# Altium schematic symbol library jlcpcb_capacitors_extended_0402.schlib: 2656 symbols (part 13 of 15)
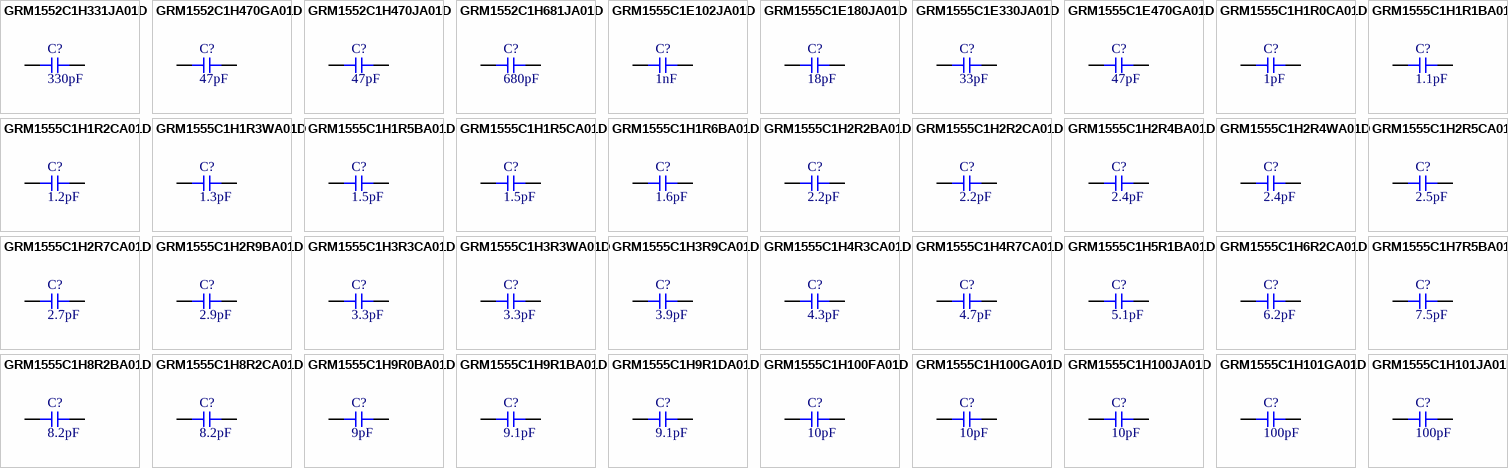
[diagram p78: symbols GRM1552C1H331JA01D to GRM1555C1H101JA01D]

## GRM1555C1H4R3CA01D
designator C?  Capacitance: 4.3pF  (hidden comment: *)
Capacitor, Ceramic (MLCC), 4.3pF, ±0.25pF, 50V, C0G, ±0.25pF, SMD 0402; Manufacturer: Murata Electronics; Manufacturer Part Number: GRM1555C1H4R3CA01D
footprint CAP-0402 (0402 (1005M) Capacitor)
pins: 1, 2

## GRM1555C1H4R7CA01D
designator C?  Capacitance: 4.7pF  (hidden comment: *)
Capacitor, Ceramic (MLCC), 4.7pF, ±0.25pF, 50V, C0G, ±0.25pF, SMD 0402; Manufacturer: Murata Electronics; Manufacturer Part Number: GRM1555C1H4R7CA01D
footprint CAP-0402 (0402 (1005M) Capacitor)
pins: 1, 2

## GRM1555C1H5R1BA01D
designator C?  Capacitance: 5.1pF  (hidden comment: *)
Capacitor, Ceramic (MLCC), 5.1pF, ±0.1pF, 50V, C0G, ±0.1pF, SMD 0402; Manufacturer: Murata Electronics; Manufacturer Part Number: GRM1555C1H5R1BA01D
footprint CAP-0402 (0402 (1005M) Capacitor)
pins: 1, 2

## GRM1555C1H6R2CA01D
designator C?  Capacitance: 6.2pF  (hidden comment: *)
Capacitor, Ceramic (MLCC), 6.2pF, ±0.25pF, 50V, C0G, ±0.25pF, SMD 0402; Manufacturer: Murata Electronics; Manufacturer Part Number: GRM1555C1H6R2CA01D
footprint CAP-0402 (0402 (1005M) Capacitor)
pins: 1, 2

## GRM1555C1H7R5BA01D
designator C?  Capacitance: 7.5pF  (hidden comment: *)
Capacitor, Ceramic (MLCC), 7.5pF, ±0.1pF, 50V, C0G, ±0.1pF, SMD 0402; Manufacturer: Murata Electronics; Manufacturer Part Number: GRM1555C1H7R5BA01D
footprint CAP-0402 (0402 (1005M) Capacitor)
pins: 1, 2

## GRM1555C1H8R2BA01D
designator C?  Capacitance: 8.2pF  (hidden comment: *)
Capacitor, Ceramic (MLCC), 8.2pF, ±0.1pF, 50V, C0G, ±0.1pF, SMD 0402; Manufacturer: Murata Electronics; Manufacturer Part Number: GRM1555C1H8R2BA01D
footprint CAP-0402 (0402 (1005M) Capacitor)
pins: 1, 2

## GRM1555C1H8R2CA01D
designator C?  Capacitance: 8.2pF  (hidden comment: *)
Capacitor, Ceramic (MLCC), 8.2pF, ±0.25pF, 50V, C0G, ±0.25pF, SMD 0402; Manufacturer: Murata Electronics; Manufacturer Part Number: GRM1555C1H8R2CA01D
footprint CAP-0402 (0402 (1005M) Capacitor)
pins: 1, 2

## GRM1555C1H9R0BA01D
designator C?  Capacitance: 9pF  (hidden comment: *)
Capacitor, Ceramic (MLCC), 9pF, ±0.1pF, 50V, C0G, ±0.1pF, SMD 0402; Manufacturer: Murata Electronics; Manufacturer Part Number: GRM1555C1H9R0BA01D
footprint CAP-0402 (0402 (1005M) Capacitor)
pins: 1, 2

## GRM1555C1H9R1BA01D
designator C?  Capacitance: 9.1pF  (hidden comment: *)
Capacitor, Ceramic (MLCC), 9.1pF, ±0.1pF, 50V, C0G, ±0.1pF, SMD 0402; Manufacturer: Murata Electronics; Manufacturer Part Number: GRM1555C1H9R1BA01D
footprint CAP-0402 (0402 (1005M) Capacitor)
pins: 1, 2

## GRM1555C1H9R1DA01D
designator C?  Capacitance: 9.1pF  (hidden comment: *)
Capacitor, Ceramic (MLCC), 9.1pF, ±0.5pF, 50V, C0G, ±0.5pF, SMD 0402; Manufacturer: Murata Electronics; Manufacturer Part Number: GRM1555C1H9R1DA01D
footprint CAP-0402 (0402 (1005M) Capacitor)
pins: 1, 2

## GRM1555C1H100FA01D
designator C?  Capacitance: 10pF  (hidden comment: *)
Capacitor, Ceramic (MLCC), 10pF, ±1%, 50V, C0G, ±1%, SMD 0402; Manufacturer: Murata Electronics; Manufacturer Part Number: GRM1555C1H100FA01D
footprint CAP-0402 (0402 (1005M) Capacitor)
pins: 1, 2

## GRM1555C1H100GA01D
designator C?  Capacitance: 10pF  (hidden comment: *)
Capacitor, Ceramic (MLCC), 10pF, ±2%, 50V, C0G, ±2%, SMD 0402; Manufacturer: Murata Electronics; Manufacturer Part Number: GRM1555C1H100GA01D
footprint CAP-0402 (0402 (1005M) Capacitor)
pins: 1, 2

## GRM1555C1H100JA01D
designator C?  Capacitance: 10pF  (hidden comment: *)
Capacitor, Ceramic (MLCC), 10pF, ±5%, 50V, C0G, ±5%, SMD 0402; Manufacturer: Murata Electronics; Manufacturer Part Number: GRM1555C1H100JA01D
footprint CAP-0402 (0402 (1005M) Capacitor)
pins: 1, 2

## GRM1555C1H101GA01D
designator C?  Capacitance: 100pF  (hidden comment: *)
Capacitor, Ceramic (MLCC), 100pF, ±2%, 50V, C0G, ±2%, SMD 0402; Manufacturer: Murata Electronics; Manufacturer Part Number: GRM1555C1H101GA01D
footprint CAP-0402 (0402 (1005M) Capacitor)
pins: 1, 2

## GRM1555C1H101JA01D
designator C?  Capacitance: 100pF  (hidden comment: *)
Capacitor, Ceramic (MLCC), 100pF, ±5%, 50V, C0G, ±5%, SMD 0402; Manufacturer: Murata Electronics; Manufacturer Part Number: GRM1555C1H101JA01D
footprint CAP-0402 (0402 (1005M) Capacitor)
pins: 1, 2

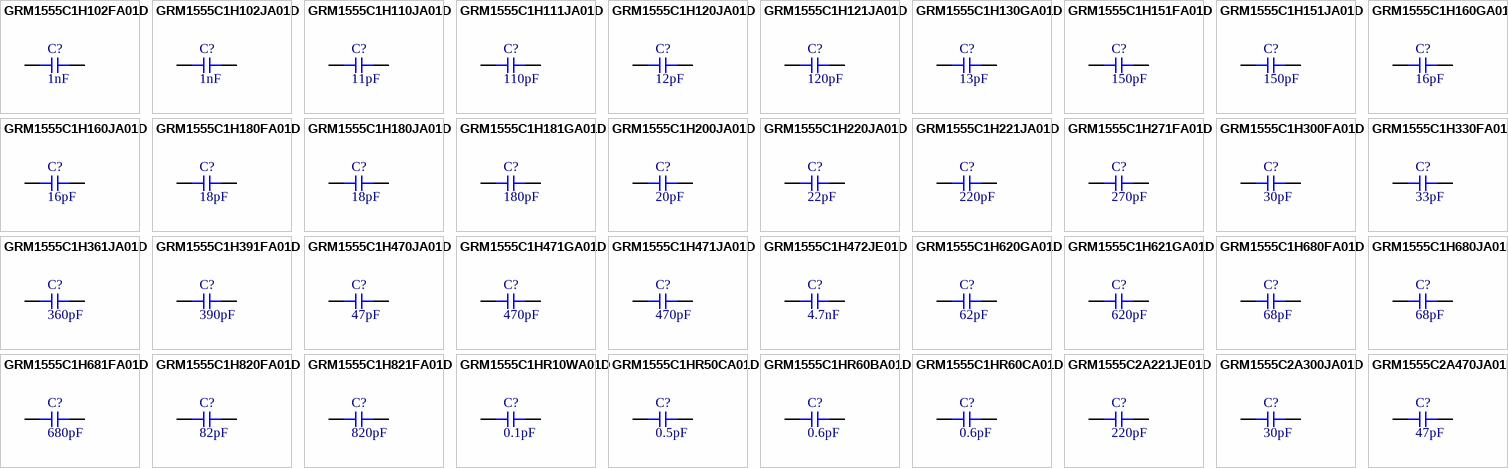
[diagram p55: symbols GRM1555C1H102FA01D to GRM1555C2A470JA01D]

## GRM1555C1H102FA01D
designator C?  Capacitance: 1nF  (hidden comment: *)
Capacitor, Ceramic (MLCC), 1nF, ±1%, 50V, C0G, ±1%, SMD 0402; Manufacturer: Murata Electronics; Manufacturer Part Number: GRM1555C1H102FA01D
footprint CAP-0402 (0402 (1005M) Capacitor)
pins: 1, 2

## GRM1555C1H102JA01D
designator C?  Capacitance: 1nF  (hidden comment: *)
Capacitor, Ceramic (MLCC), 1nF, ±5%, 50V, C0G, ±5%, SMD 0402; Manufacturer: Murata Electronics; Manufacturer Part Number: GRM1555C1H102JA01D
footprint CAP-0402 (0402 (1005M) Capacitor)
pins: 1, 2

## GRM1555C1H110JA01D
designator C?  Capacitance: 11pF  (hidden comment: *)
Capacitor, Ceramic (MLCC), 11pF, ±5%, 50V, C0G, ±5%, SMD 0402; Manufacturer: Murata Electronics; Manufacturer Part Number: GRM1555C1H110JA01D
footprint CAP-0402 (0402 (1005M) Capacitor)
pins: 1, 2

## GRM1555C1H111JA01D
designator C?  Capacitance: 110pF  (hidden comment: *)
Capacitor, Ceramic (MLCC), 110pF, ±5%, 50V, ±5%, SMD 0402; Manufacturer: Murata Electronics; Manufacturer Part Number: GRM1555C1H111JA01D
footprint CAP-0402 (0402 (1005M) Capacitor)
pins: 1, 2

## GRM1555C1H120JA01D
designator C?  Capacitance: 12pF  (hidden comment: *)
Capacitor, Ceramic (MLCC), 12pF, ±5%, 50V, C0G, ±5%, SMD 0402; Manufacturer: Murata Electronics; Manufacturer Part Number: GRM1555C1H120JA01D
footprint CAP-0402 (0402 (1005M) Capacitor)
pins: 1, 2

## GRM1555C1H121JA01D
designator C?  Capacitance: 120pF  (hidden comment: *)
Capacitor, Ceramic (MLCC), 120pF, ±5%, 50V, C0G, ±5%, SMD 0402; Manufacturer: Murata Electronics; Manufacturer Part Number: GRM1555C1H121JA01D
footprint CAP-0402 (0402 (1005M) Capacitor)
pins: 1, 2

## GRM1555C1H130GA01D
designator C?  Capacitance: 13pF  (hidden comment: *)
Capacitor, Ceramic (MLCC), 13pF, ±2%, 50V, C0G, ±2%, SMD 0402; Manufacturer: Murata Electronics; Manufacturer Part Number: GRM1555C1H130GA01D
footprint CAP-0402 (0402 (1005M) Capacitor)
pins: 1, 2

## GRM1555C1H151FA01D
designator C?  Capacitance: 150pF  (hidden comment: *)
Capacitor, Ceramic (MLCC), 150pF, ±1%, 50V, C0G, ±1%, SMD 0402; Manufacturer: Murata Electronics; Manufacturer Part Number: GRM1555C1H151FA01D
footprint CAP-0402 (0402 (1005M) Capacitor)
pins: 1, 2

## GRM1555C1H151JA01D
designator C?  Capacitance: 150pF  (hidden comment: *)
Capacitor, Ceramic (MLCC), 150pF, ±5%, 50V, C0G, ±5%, SMD 0402; Manufacturer: Murata Electronics; Manufacturer Part Number: GRM1555C1H151JA01D
footprint CAP-0402 (0402 (1005M) Capacitor)
pins: 1, 2

## GRM1555C1H160GA01D
designator C?  Capacitance: 16pF  (hidden comment: *)
Capacitor, Ceramic (MLCC), 16pF, ±2%, 50V, C0G, ±2%, SMD 0402; Manufacturer: Murata Electronics; Manufacturer Part Number: GRM1555C1H160GA01D
footprint CAP-0402 (0402 (1005M) Capacitor)
pins: 1, 2

## GRM1555C1H160JA01D
designator C?  Capacitance: 16pF  (hidden comment: *)
Capacitor, Ceramic (MLCC), 16pF, ±5%, 50V, C0G, ±5%, SMD 0402; Manufacturer: Murata Electronics; Manufacturer Part Number: GRM1555C1H160JA01D
footprint CAP-0402 (0402 (1005M) Capacitor)
pins: 1, 2

## GRM1555C1H180FA01D
designator C?  Capacitance: 18pF  (hidden comment: *)
Capacitor, Ceramic (MLCC), 18pF, ±1%, 50V, C0G, ±1%, SMD 0402; Manufacturer: Murata Electronics; Manufacturer Part Number: GRM1555C1H180FA01D
footprint CAP-0402 (0402 (1005M) Capacitor)
pins: 1, 2

## GRM1555C1H180JA01D
designator C?  Capacitance: 18pF  (hidden comment: *)
Capacitor, Ceramic (MLCC), 18pF, ±5%, 50V, C0G, ±5%, SMD 0402; Manufacturer: Murata Electronics; Manufacturer Part Number: GRM1555C1H180JA01D
footprint CAP-0402 (0402 (1005M) Capacitor)
pins: 1, 2

## GRM1555C1H181GA01D
designator C?  Capacitance: 180pF  (hidden comment: *)
Capacitor, Ceramic (MLCC), 180pF, ±2%, 50V, C0G, ±2%, SMD 0402; Manufacturer: Murata Electronics; Manufacturer Part Number: GRM1555C1H181GA01D
footprint CAP-0402 (0402 (1005M) Capacitor)
pins: 1, 2

## GRM1555C1H200JA01D
designator C?  Capacitance: 20pF  (hidden comment: *)
Capacitor, Ceramic (MLCC), 20pF, ±5%, 50V, C0G, ±5%, SMD 0402; Manufacturer: Murata Electronics; Manufacturer Part Number: GRM1555C1H200JA01D
footprint CAP-0402 (0402 (1005M) Capacitor)
pins: 1, 2

## GRM1555C1H220JA01D
designator C?  Capacitance: 22pF  (hidden comment: *)
Capacitor, Ceramic (MLCC), 22pF, ±5%, 50V, C0G, ±5%, SMD 0402; Manufacturer: Murata Electronics; Manufacturer Part Number: GRM1555C1H220JA01D
footprint CAP-0402 (0402 (1005M) Capacitor)
pins: 1, 2

## GRM1555C1H221JA01D
designator C?  Capacitance: 220pF  (hidden comment: *)
Capacitor, Ceramic (MLCC), 220pF, ±5%, 50V, C0G, ±5%, SMD 0402; Manufacturer: Murata Electronics; Manufacturer Part Number: GRM1555C1H221JA01D
footprint CAP-0402 (0402 (1005M) Capacitor)
pins: 1, 2

## GRM1555C1H271FA01D
designator C?  Capacitance: 270pF  (hidden comment: *)
Capacitor, Ceramic (MLCC), 270pF, ±1%, 50V, C0G, ±1%, SMD 0402; Manufacturer: Murata Electronics; Manufacturer Part Number: GRM1555C1H271FA01D
footprint CAP-0402 (0402 (1005M) Capacitor)
pins: 1, 2

## GRM1555C1H300FA01D
designator C?  Capacitance: 30pF  (hidden comment: *)
Capacitor, Ceramic (MLCC), 30pF, ±1%, 50V, C0G, ±1%, SMD 0402; Manufacturer: Murata Electronics; Manufacturer Part Number: GRM1555C1H300FA01D
footprint CAP-0402 (0402 (1005M) Capacitor)
pins: 1, 2

## GRM1555C1H330FA01D
designator C?  Capacitance: 33pF  (hidden comment: *)
Capacitor, Ceramic (MLCC), 33pF, ±1%, 50V, ±1%, SMD 0402; Manufacturer: Murata Electronics; Manufacturer Part Number: GRM1555C1H330FA01D
footprint CAP-0402 (0402 (1005M) Capacitor)
pins: 1, 2

## GRM1555C1H361JA01D
designator C?  Capacitance: 360pF  (hidden comment: *)
Capacitor, Ceramic (MLCC), 360pF, ±5%, 50V, C0G, ±5%, SMD 0402; Manufacturer: Murata Electronics; Manufacturer Part Number: GRM1555C1H361JA01D
footprint CAP-0402 (0402 (1005M) Capacitor)
pins: 1, 2

## GRM1555C1H391FA01D
designator C?  Capacitance: 390pF  (hidden comment: *)
Capacitor, Ceramic (MLCC), 390pF, ±1%, 50V, C0G, ±1%, SMD 0402; Manufacturer: Murata Electronics; Manufacturer Part Number: GRM1555C1H391FA01D
footprint CAP-0402 (0402 (1005M) Capacitor)
pins: 1, 2

## GRM1555C1H470JA01D
designator C?  Capacitance: 47pF  (hidden comment: *)
Capacitor, Ceramic (MLCC), 47pF, ±5%, 50V, C0G, ±5%, SMD 0402; Manufacturer: Murata Electronics; Manufacturer Part Number: GRM1555C1H470JA01D
footprint CAP-0402 (0402 (1005M) Capacitor)
pins: 1, 2

## GRM1555C1H471GA01D
designator C?  Capacitance: 470pF  (hidden comment: *)
Capacitor, Ceramic (MLCC), 470pF, ±2%, ±2%, SMD 0402; Manufacturer: Murata Electronics; Manufacturer Part Number: GRM1555C1H471GA01D
footprint CAP-0402 (0402 (1005M) Capacitor)
pins: 1, 2

## GRM1555C1H471JA01D
designator C?  Capacitance: 470pF  (hidden comment: *)
Capacitor, Ceramic (MLCC), 470pF, ±5%, 50V, C0G, ±5%, SMD 0402; Manufacturer: Murata Electronics; Manufacturer Part Number: GRM1555C1H471JA01D
footprint CAP-0402 (0402 (1005M) Capacitor)
pins: 1, 2

## GRM1555C1H472JE01D
designator C?  Capacitance: 4.7nF  (hidden comment: *)
Capacitor, Ceramic (MLCC), 4.7nF, ±5%, 50V, C0G, ±5%, SMD 0402; Manufacturer: Murata Electronics; Manufacturer Part Number: GRM1555C1H472JE01D
footprint CAP-0402 (0402 (1005M) Capacitor)
pins: 1, 2

## GRM1555C1H620GA01D
designator C?  Capacitance: 62pF  (hidden comment: *)
Capacitor, Ceramic (MLCC), 62pF, ±2%, 50V, C0G, ±2%, SMD 0402; Manufacturer: Murata Electronics; Manufacturer Part Number: GRM1555C1H620GA01D
footprint CAP-0402 (0402 (1005M) Capacitor)
pins: 1, 2

## GRM1555C1H621GA01D
designator C?  Capacitance: 620pF  (hidden comment: *)
Capacitor, Ceramic (MLCC), 620pF, ±2%, 50V, C0G, ±2%, SMD 0402; Manufacturer: Murata Electronics; Manufacturer Part Number: GRM1555C1H621GA01D
footprint CAP-0402 (0402 (1005M) Capacitor)
pins: 1, 2

## GRM1555C1H680FA01D
designator C?  Capacitance: 68pF  (hidden comment: *)
Capacitor, Ceramic (MLCC), 68pF, ±1%, 50V, C0G, ±1%, SMD 0402; Manufacturer: Murata Electronics; Manufacturer Part Number: GRM1555C1H680FA01D
footprint CAP-0402 (0402 (1005M) Capacitor)
pins: 1, 2

## GRM1555C1H680JA01D
designator C?  Capacitance: 68pF  (hidden comment: *)
Capacitor, Ceramic (MLCC), 68pF, ±5%, 50V, C0G, ±5%, SMD 0402; Manufacturer: Murata Electronics; Manufacturer Part Number: GRM1555C1H680JA01D
footprint CAP-0402 (0402 (1005M) Capacitor)
pins: 1, 2

## GRM1555C1H681FA01D
designator C?  Capacitance: 680pF  (hidden comment: *)
Capacitor, Ceramic (MLCC), 680pF, ±1%, ±1%, SMD 0402; Manufacturer: Murata Electronics; Manufacturer Part Number: GRM1555C1H681FA01D
footprint CAP-0402 (0402 (1005M) Capacitor)
pins: 1, 2

## GRM1555C1H820FA01D
designator C?  Capacitance: 82pF  (hidden comment: *)
Capacitor, Ceramic (MLCC), 82pF, ±1%, 50V, C0G, ±1%, SMD 0402; Manufacturer: Murata Electronics; Manufacturer Part Number: GRM1555C1H820FA01D
footprint CAP-0402 (0402 (1005M) Capacitor)
pins: 1, 2

## GRM1555C1H821FA01D
designator C?  Capacitance: 820pF  (hidden comment: *)
Capacitor, Ceramic (MLCC), 820pF, ±1%, ±1%, SMD 0402; Manufacturer: Murata Electronics; Manufacturer Part Number: GRM1555C1H821FA01D
footprint CAP-0402 (0402 (1005M) Capacitor)
pins: 1, 2

## GRM1555C1HR10WA01D
designator C?  Capacitance: 0.1pF  (hidden comment: *)
Capacitor, Ceramic (MLCC), 0.1pF, ±0.05pF, 50V, C0G, ±0.05pF, SMD 0402; Manufacturer: Murata Electronics; Manufacturer Part Number: GRM1555C1HR10WA01D
footprint CAP-0402 (0402 (1005M) Capacitor)
pins: 1, 2

## GRM1555C1HR50CA01D
designator C?  Capacitance: 0.5pF  (hidden comment: *)
Capacitor, Ceramic (MLCC), 0.5pF, ±0.25pF, 50V, C0G, ±0.25pF, SMD 0402; Manufacturer: Murata Electronics; Manufacturer Part Number: GRM1555C1HR50CA01D
footprint CAP-0402 (0402 (1005M) Capacitor)
pins: 1, 2

## GRM1555C1HR60BA01D
designator C?  Capacitance: 0.6pF  (hidden comment: *)
Capacitor, Ceramic (MLCC), 0.6pF, ±0.1pF, 50V, C0G, ±0.1pF, SMD 0402; Manufacturer: Murata Electronics; Manufacturer Part Number: GRM1555C1HR60BA01D
footprint CAP-0402 (0402 (1005M) Capacitor)
pins: 1, 2

## GRM1555C1HR60CA01D
designator C?  Capacitance: 0.6pF  (hidden comment: *)
Capacitor, Ceramic (MLCC), 0.6pF, ±0.25pF, 50V, C0G, ±0.25pF, SMD 0402; Manufacturer: Murata Electronics; Manufacturer Part Number: GRM1555C1HR60CA01D
footprint CAP-0402 (0402 (1005M) Capacitor)
pins: 1, 2

## GRM1555C2A221JE01D
designator C?  Capacitance: 220pF  (hidden comment: *)
Capacitor, Ceramic (MLCC), 220pF, ±5%, 100V, C0G, ±5%, SMD 0402; Manufacturer: Murata Electronics; Manufacturer Part Number: GRM1555C2A221JE01D
footprint CAP-0402 (0402 (1005M) Capacitor)
pins: 1, 2

## GRM1555C2A300JA01D
designator C?  Capacitance: 30pF  (hidden comment: *)
Capacitor, Ceramic (MLCC), 30pF, ±5%, ±5%, SMD 0402; Manufacturer: Murata Electronics; Manufacturer Part Number: GRM1555C2A300JA01D
footprint CAP-0402 (0402 (1005M) Capacitor)
pins: 1, 2

## GRM1555C2A470JA01D
designator C?  Capacitance: 47pF  (hidden comment: *)
Capacitor, Ceramic (MLCC), 47pF, ±5%, 100V, C0G, ±5%, SMD 0402; Manufacturer: Murata Electronics; Manufacturer Part Number: GRM1555C2A470JA01D
footprint CAP-0402 (0402 (1005M) Capacitor)
pins: 1, 2

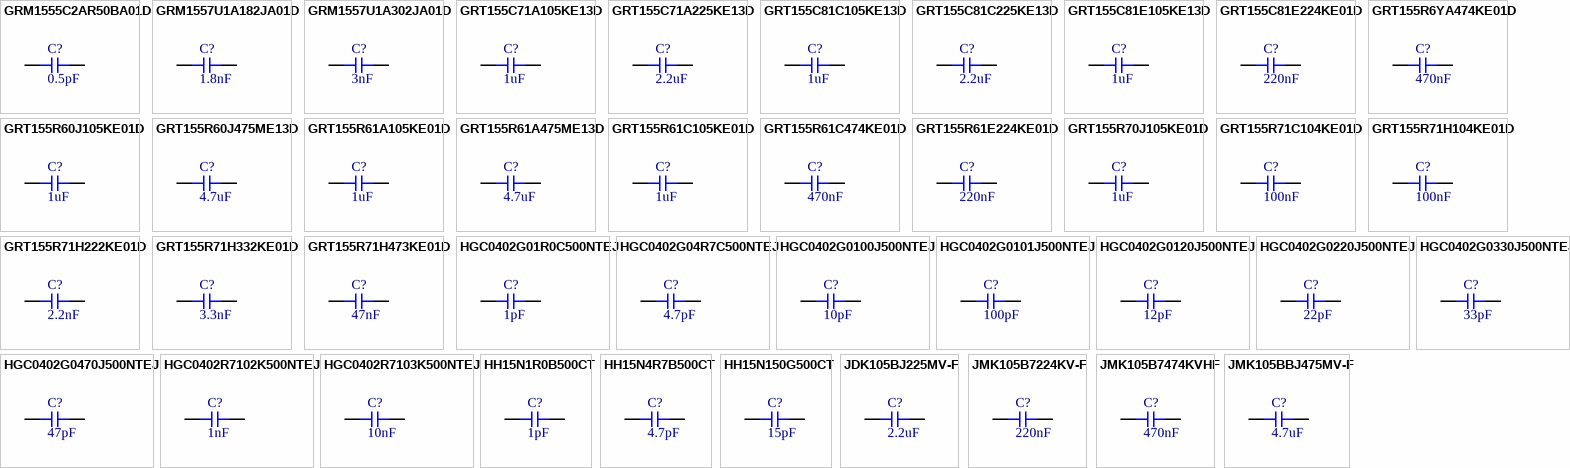
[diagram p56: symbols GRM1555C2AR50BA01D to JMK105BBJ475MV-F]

## GRM1555C2AR50BA01D
designator C?  Capacitance: 0.5pF  (hidden comment: *)
Capacitor, Ceramic (MLCC), 0.5pF, ±0.1pF, 100V, C0G, ±0.1pF, SMD 0402; Manufacturer: Murata Electronics; Manufacturer Part Number: GRM1555C2AR50BA01D
footprint CAP-0402 (0402 (1005M) Capacitor)
pins: 1, 2

## GRM1557U1A182JA01D
designator C?  Capacitance: 1.8nF  (hidden comment: *)
Capacitor, Ceramic (MLCC), 1.8nF, ±5%, 10V, U2J, ±5%, SMD 0402; Manufacturer: Murata Electronics; Manufacturer Part Number: GRM1557U1A182JA01D
footprint CAP-0402 (0402 (1005M) Capacitor)
pins: 1, 2

## GRM1557U1A302JA01D
designator C?  Capacitance: 3nF  (hidden comment: *)
Capacitor, Ceramic (MLCC), 3nF, ±5%, 10V, U2J, ±5%, SMD 0402; Manufacturer: Murata Electronics; Manufacturer Part Number: GRM1557U1A302JA01D
footprint CAP-0402 (0402 (1005M) Capacitor)
pins: 1, 2

## GRT155C71A105KE13D
designator C?  Capacitance: 1uF  (hidden comment: *)
Capacitor, Ceramic (MLCC), 1uF, ±10%, ±10%, SMD 0402; Manufacturer: Murata Electronics; Manufacturer Part Number: GRT155C71A105KE13D
footprint CAP-0402 (0402 (1005M) Capacitor)
pins: 1, 2

## GRT155C71A225KE13D
designator C?  Capacitance: 2.2uF  (hidden comment: *)
Capacitor, Ceramic (MLCC), 2.2uF, ±10%, 10V, X7S, ±10%, SMD 0402; Manufacturer: Murata Electronics; Manufacturer Part Number: GRT155C71A225KE13D
footprint CAP-0402 (0402 (1005M) Capacitor)
pins: 1, 2

## GRT155C81C105KE13D
designator C?  Capacitance: 1uF  (hidden comment: *)
Capacitor, Ceramic (MLCC), 1uF, ±10%, ±10%, SMD 0402; Manufacturer: Murata Electronics; Manufacturer Part Number: GRT155C81C105KE13D
footprint CAP-0402 (0402 (1005M) Capacitor)
pins: 1, 2

## GRT155C81C225KE13D
designator C?  Capacitance: 2.2uF  (hidden comment: *)
Capacitor, Ceramic (MLCC), 2.2uF, ±10%, ±10%, SMD 0402; Manufacturer: Murata Electronics; Manufacturer Part Number: GRT155C81C225KE13D
footprint CAP-0402 (0402 (1005M) Capacitor)
pins: 1, 2

## GRT155C81E105KE13D
designator C?  Capacitance: 1uF  (hidden comment: *)
Capacitor, Ceramic (MLCC), 1uF, ±10%, ±10%, SMD 0402; Manufacturer: Murata Electronics; Manufacturer Part Number: GRT155C81E105KE13D
footprint CAP-0402 (0402 (1005M) Capacitor)
pins: 1, 2

## GRT155C81E224KE01D
designator C?  Capacitance: 220nF  (hidden comment: *)
Capacitor, Ceramic (MLCC), 220nF, ±10%, 25V, X6S, ±10%, SMD 0402; Manufacturer: Murata Electronics; Manufacturer Part Number: GRT155C81E224KE01D
footprint CAP-0402 (0402 (1005M) Capacitor)
pins: 1, 2

## GRT155R6YA474KE01D
designator C?  Capacitance: 470nF  (hidden comment: *)
Capacitor, Ceramic (MLCC), 470nF, ±10%, ±10%, SMD 0402; Manufacturer: Murata Electronics; Manufacturer Part Number: GRT155R6YA474KE01D
footprint CAP-0402 (0402 (1005M) Capacitor)
pins: 1, 2

## GRT155R60J105KE01D
designator C?  Capacitance: 1uF  (hidden comment: *)
Capacitor, Ceramic (MLCC), 1uF, ±10%, 6.3V, X5R, ±10%, SMD 0402; Manufacturer: Murata Electronics; Manufacturer Part Number: GRT155R60J105KE01D
footprint CAP-0402 (0402 (1005M) Capacitor)
pins: 1, 2

## GRT155R60J475ME13D
designator C?  Capacitance: 4.7uF  (hidden comment: *)
Capacitor, Ceramic (MLCC), 4.7uF, ±20%, 6.3V, X5R, ±20%, SMD 0402; Manufacturer: Murata Electronics; Manufacturer Part Number: GRT155R60J475ME13D
footprint CAP-0402 (0402 (1005M) Capacitor)
pins: 1, 2

## GRT155R61A105KE01D
designator C?  Capacitance: 1uF  (hidden comment: *)
Capacitor, Ceramic (MLCC), 1uF, ±10%, 10V, X5R, ±10%, SMD 0402; Manufacturer: Murata Electronics; Manufacturer Part Number: GRT155R61A105KE01D
footprint CAP-0402 (0402 (1005M) Capacitor)
pins: 1, 2

## GRT155R61A475ME13D
designator C?  Capacitance: 4.7uF  (hidden comment: *)
Capacitor, Ceramic (MLCC), 4.7uF, ±20%, ±20%, SMD 0402; Manufacturer: Murata Electronics; Manufacturer Part Number: GRT155R61A475ME13D
footprint CAP-0402 (0402 (1005M) Capacitor)
pins: 1, 2

## GRT155R61C105KE01D
designator C?  Capacitance: 1uF  (hidden comment: *)
Capacitor, Ceramic (MLCC), 1uF, ±10%, 16V, X5R, ±10%, SMD 0402; Manufacturer: Murata Electronics; Manufacturer Part Number: GRT155R61C105KE01D
footprint CAP-0402 (0402 (1005M) Capacitor)
pins: 1, 2

## GRT155R61C474KE01D
designator C?  Capacitance: 470nF  (hidden comment: *)
Capacitor, Ceramic (MLCC), 470nF, ±10%, 16V, X5R, ±10%, SMD 0402; Manufacturer: Murata Electronics; Manufacturer Part Number: GRT155R61C474KE01D
footprint CAP-0402 (0402 (1005M) Capacitor)
pins: 1, 2

## GRT155R61E224KE01D
designator C?  Capacitance: 220nF  (hidden comment: *)
Capacitor, Ceramic (MLCC), 220nF, ±10%, 25V, ±10%, SMD 0402; Manufacturer: Murata Electronics; Manufacturer Part Number: GRT155R61E224KE01D
footprint CAP-0402 (0402 (1005M) Capacitor)
pins: 1, 2

## GRT155R70J105KE01D
designator C?  Capacitance: 1uF  (hidden comment: *)
Capacitor, Ceramic (MLCC), 1uF, ±10%, ±10%, SMD 0402; Manufacturer: Murata Electronics; Manufacturer Part Number: GRT155R70J105KE01D
footprint CAP-0402 (0402 (1005M) Capacitor)
pins: 1, 2

## GRT155R71C104KE01D
designator C?  Capacitance: 100nF  (hidden comment: *)
Capacitor, Ceramic (MLCC), 100nF, ±10%, ±10%, SMD 0402; Manufacturer: Murata Electronics; Manufacturer Part Number: GRT155R71C104KE01D
footprint CAP-0402 (0402 (1005M) Capacitor)
pins: 1, 2

## GRT155R71H104KE01D
designator C?  Capacitance: 100nF  (hidden comment: *)
Capacitor, Ceramic (MLCC), 100nF, ±10%, ±10%, SMD 0402; Manufacturer: Murata Electronics; Manufacturer Part Number: GRT155R71H104KE01D
footprint CAP-0402 (0402 (1005M) Capacitor)
pins: 1, 2

## GRT155R71H222KE01D
designator C?  Capacitance: 2.2nF  (hidden comment: *)
Capacitor, Ceramic (MLCC), 2.2nF, ±10%, ±10%, SMD 0402; Manufacturer: Murata Electronics; Manufacturer Part Number: GRT155R71H222KE01D
footprint CAP-0402 (0402 (1005M) Capacitor)
pins: 1, 2

## GRT155R71H332KE01D
designator C?  Capacitance: 3.3nF  (hidden comment: *)
Capacitor, Ceramic (MLCC), 3.3nF, ±10%, ±10%, SMD 0402; Manufacturer: Murata Electronics; Manufacturer Part Number: GRT155R71H332KE01D
footprint CAP-0402 (0402 (1005M) Capacitor)
pins: 1, 2

## GRT155R71H473KE01D
designator C?  Capacitance: 47nF  (hidden comment: *)
Capacitor, Ceramic (MLCC), 47nF, ±10%, ±10%, SMD 0402; Manufacturer: Murata Electronics; Manufacturer Part Number: GRT155R71H473KE01D
footprint CAP-0402 (0402 (1005M) Capacitor)
pins: 1, 2

## HGC0402G01R0C500NTEJ
designator C?  Capacitance: 1pF  (hidden comment: *)
Capacitor, Ceramic (MLCC), 1pF, ±0.25pF, 50V, C0G, ±0.25pF, SMD 0402; Manufacturer: Chinocera; Manufacturer Part Number: HGC0402G01R0C500NTEJ
footprint CAP-0402 (0402 (1005M) Capacitor)
pins: 1, 2

## HGC0402G04R7C500NTEJ
designator C?  Capacitance: 4.7pF  (hidden comment: *)
Capacitor, Ceramic (MLCC), 4.7pF, ±0.25pF, 50V, C0G, ±0.25pF, SMD 0402; Manufacturer: Chinocera; Manufacturer Part Number: HGC0402G04R7C500NTEJ
footprint CAP-0402 (0402 (1005M) Capacitor)
pins: 1, 2

## HGC0402G0100J500NTEJ
designator C?  Capacitance: 10pF  (hidden comment: *)
Capacitor, Ceramic (MLCC), 10pF, ±5%, 50V, C0G, ±5%, SMD 0402; Manufacturer: Chinocera; Manufacturer Part Number: HGC0402G0100J500NTEJ
footprint CAP-0402 (0402 (1005M) Capacitor)
pins: 1, 2

## HGC0402G0101J500NTEJ
designator C?  Capacitance: 100pF  (hidden comment: *)
Capacitor, Ceramic (MLCC), 100pF, ±5%, 50V, C0G, ±5%, SMD 0402; Manufacturer: Chinocera; Manufacturer Part Number: HGC0402G0101J500NTEJ
footprint CAP-0402 (0402 (1005M) Capacitor)
pins: 1, 2

## HGC0402G0120J500NTEJ
designator C?  Capacitance: 12pF  (hidden comment: *)
Capacitor, Ceramic (MLCC), 12pF, ±5%, 50V, C0G, ±5%, SMD 0402; Manufacturer: Chinocera; Manufacturer Part Number: HGC0402G0120J500NTEJ
footprint CAP-0402 (0402 (1005M) Capacitor)
pins: 1, 2

## HGC0402G0220J500NTEJ
designator C?  Capacitance: 22pF  (hidden comment: *)
Capacitor, Ceramic (MLCC), 22pF, ±5%, 50V, C0G, ±5%, SMD 0402; Manufacturer: Chinocera; Manufacturer Part Number: HGC0402G0220J500NTEJ
footprint CAP-0402 (0402 (1005M) Capacitor)
pins: 1, 2

## HGC0402G0330J500NTEJ
designator C?  Capacitance: 33pF  (hidden comment: *)
Capacitor, Ceramic (MLCC), 33pF, ±5%, 50V, C0G, ±5%, SMD 0402; Manufacturer: Chinocera; Manufacturer Part Number: HGC0402G0330J500NTEJ
footprint CAP-0402 (0402 (1005M) Capacitor)
pins: 1, 2

## HGC0402G0470J500NTEJ
designator C?  Capacitance: 47pF  (hidden comment: *)
Capacitor, Ceramic (MLCC), 47pF, ±5%, 50V, C0G, ±5%, SMD 0402; Manufacturer: Chinocera; Manufacturer Part Number: HGC0402G0470J500NTEJ
footprint CAP-0402 (0402 (1005M) Capacitor)
pins: 1, 2

## HGC0402R7102K500NTEJ
designator C?  Capacitance: 1nF  (hidden comment: *)
Capacitor, Ceramic (MLCC), 1nF, ±10%, 50V, X7R, ±10%, SMD 0402; Manufacturer: Chinocera; Manufacturer Part Number: HGC0402R7102K500NTEJ
footprint CAP-0402 (0402 (1005M) Capacitor)
pins: 1, 2

## HGC0402R7103K500NTEJ
designator C?  Capacitance: 10nF  (hidden comment: *)
Capacitor, Ceramic (MLCC), 10nF, ±10%, 50V, X7R, ±10%, SMD 0402; Manufacturer: Chinocera; Manufacturer Part Number: HGC0402R7103K500NTEJ
footprint CAP-0402 (0402 (1005M) Capacitor)
pins: 1, 2

## HH15N1R0B500CT
designator C?  Capacitance: 1pF  (hidden comment: *)
Capacitor, Ceramic (MLCC), 1pF, ±0.1pF, 50V, NP0, ±0.1pF, SMD 0402; Manufacturer: Walsin Tech Corp; Manufacturer Part Number: HH15N1R0B500CT
footprint CAP-0402 (0402 (1005M) Capacitor)
pins: 1, 2

## HH15N4R7B500CT
designator C?  Capacitance: 4.7pF  (hidden comment: *)
Capacitor, Ceramic (MLCC), 4.7pF, ±0.1pF, 50V, NP0, ±0.1pF, SMD 0402; Manufacturer: Walsin Tech Corp; Manufacturer Part Number: HH15N4R7B500CT
footprint CAP-0402 (0402 (1005M) Capacitor)
pins: 1, 2

## HH15N150G500CT
designator C?  Capacitance: 15pF  (hidden comment: *)
Capacitor, Ceramic (MLCC), 15pF, ±2%, 50V, NP0, ±2%, SMD 0402; Manufacturer: Walsin Tech Corp; Manufacturer Part Number: HH15N150G500CT
footprint CAP-0402 (0402 (1005M) Capacitor)
pins: 1, 2

## JDK105BJ225MV-F
designator C?  Capacitance: 2.2uF  (hidden comment: *)
Capacitor, Ceramic (MLCC), 2.2uF, ±20%, 6.3V, X5R, ±20%, SMD 0402; Manufacturer: Taiyo Yuden; Manufacturer Part Number: JDK105BJ225MV-F
footprint CAP-0402 (0402 (1005M) Capacitor)
pins: 1, 2

## JMK105B7224KV-F
designator C?  Capacitance: 220nF  (hidden comment: *)
Capacitor, Ceramic (MLCC), 220nF, ±10%, 6.3V, X7R, ±10%, SMD 0402; Manufacturer: Taiyo Yuden; Manufacturer Part Number: JMK105B7224KV-F
footprint CAP-0402 (0402 (1005M) Capacitor)
pins: 1, 2

## JMK105B7474KVHF
designator C?  Capacitance: 470nF  (hidden comment: *)
Capacitor, Ceramic (MLCC), 470nF, ±10%, 6.3V, X7R, ±10%, SMD 0402; Manufacturer: Taiyo Yuden; Manufacturer Part Number: JMK105B7474KVHF
footprint CAP-0402 (0402 (1005M) Capacitor)
pins: 1, 2

## JMK105BBJ475MV-F
designator C?  Capacitance: 4.7uF  (hidden comment: *)
Capacitor, Ceramic (MLCC), 4.7uF, ±20%, 6.3V, X5R, ±20%, SMD 0402; Manufacturer: Taiyo Yuden; Manufacturer Part Number: JMK105BBJ475MV-F
footprint CAP-0402 (0402 (1005M) Capacitor)
pins: 1, 2

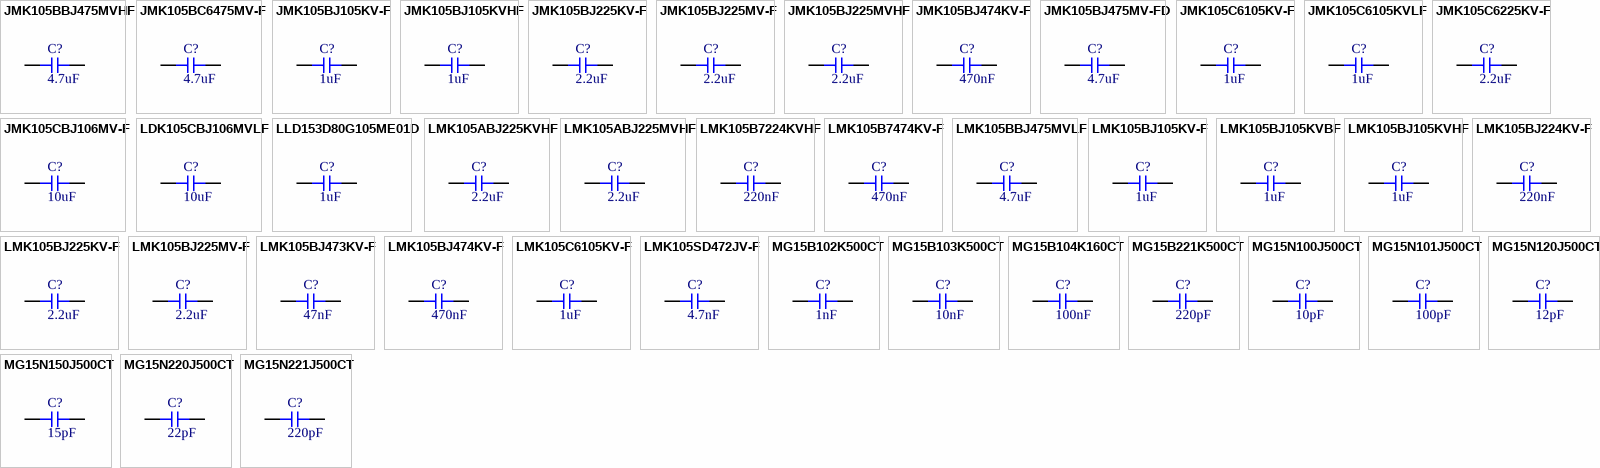
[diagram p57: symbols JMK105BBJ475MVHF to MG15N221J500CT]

## JMK105BBJ475MVHF
designator C?  Capacitance: 4.7uF  (hidden comment: *)
Capacitor, Ceramic (MLCC), 4.7uF, ±20%, 6.3V, X5R, ±20%, SMD 0402; Manufacturer: Taiyo Yuden; Manufacturer Part Number: JMK105BBJ475MVHF
footprint CAP-0402 (0402 (1005M) Capacitor)
pins: 1, 2

## JMK105BC6475MV-F
designator C?  Capacitance: 4.7uF  (hidden comment: *)
Capacitor, Ceramic (MLCC), 4.7uF, ±20%, 6.3V, X6S, ±20%, SMD 0402; Manufacturer: Taiyo Yuden; Manufacturer Part Number: JMK105BC6475MV-F
footprint CAP-0402 (0402 (1005M) Capacitor)
pins: 1, 2

## JMK105BJ105KV-F
designator C?  Capacitance: 1uF  (hidden comment: *)
Capacitor, Ceramic (MLCC), 1uF, ±10%, 6.3V, X5R, ±10%, SMD 0402; Manufacturer: Taiyo Yuden; Manufacturer Part Number: JMK105BJ105KV-F
footprint CAP-0402 (0402 (1005M) Capacitor)
pins: 1, 2

## JMK105BJ105KVHF
designator C?  Capacitance: 1uF  (hidden comment: *)
Capacitor, Ceramic (MLCC), 1uF, ±10%, 6.3V, X5R, ±10%, SMD 0402; Manufacturer: Taiyo Yuden; Manufacturer Part Number: JMK105BJ105KVHF
footprint CAP-0402 (0402 (1005M) Capacitor)
pins: 1, 2

## JMK105BJ225KV-F
designator C?  Capacitance: 2.2uF  (hidden comment: *)
Capacitor, Ceramic (MLCC), 2.2uF, ±10%, 6.3V, X5R, ±10%, SMD 0402; Manufacturer: Taiyo Yuden; Manufacturer Part Number: JMK105BJ225KV-F
footprint CAP-0402 (0402 (1005M) Capacitor)
pins: 1, 2

## JMK105BJ225MV-F
designator C?  Capacitance: 2.2uF  (hidden comment: *)
Capacitor, Ceramic (MLCC), 2.2uF, ±20%, 6.3V, X5R, ±20%, SMD 0402; Manufacturer: Taiyo Yuden; Manufacturer Part Number: JMK105BJ225MV-F
footprint CAP-0402 (0402 (1005M) Capacitor)
pins: 1, 2

## JMK105BJ225MVHF
designator C?  Capacitance: 2.2uF  (hidden comment: *)
Capacitor, Ceramic (MLCC), 2.2uF, ±20%, 6.3V, X5R, ±20%, SMD 0402; Manufacturer: Taiyo Yuden; Manufacturer Part Number: JMK105BJ225MVHF
footprint CAP-0402 (0402 (1005M) Capacitor)
pins: 1, 2

## JMK105BJ474KV-F
designator C?  Capacitance: 470nF  (hidden comment: *)
Capacitor, Ceramic (MLCC), 470nF, ±10%, 6.3V, X5R, ±10%, SMD 0402; Manufacturer: Taiyo Yuden; Manufacturer Part Number: JMK105BJ474KV-F
footprint CAP-0402 (0402 (1005M) Capacitor)
pins: 1, 2

## JMK105BJ475MV-FD
designator C?  Capacitance: 4.7uF  (hidden comment: *)
Capacitor, Ceramic (MLCC), 4.7uF, ±20%, 6.3V, ±20%, SMD 0402; Manufacturer: Taiyo Yuden; Manufacturer Part Number: JMK105BJ475MV-FD
footprint CAP-0402 (0402 (1005M) Capacitor)
pins: 1, 2

## JMK105C6105KV-F
designator C?  Capacitance: 1uF  (hidden comment: *)
Capacitor, Ceramic (MLCC), 1uF, ±10%, 6.3V, X6S, ±10%, SMD 0402; Manufacturer: Taiyo Yuden; Manufacturer Part Number: JMK105C6105KV-F
footprint CAP-0402 (0402 (1005M) Capacitor)
pins: 1, 2

## JMK105C6105KVLF
designator C?  Capacitance: 1uF  (hidden comment: *)
Capacitor, Ceramic (MLCC), 1uF, ±10%, 6.3V, X6S, ±10%, SMD 0402; Manufacturer: Taiyo Yuden; Manufacturer Part Number: JMK105C6105KVLF
footprint CAP-0402 (0402 (1005M) Capacitor)
pins: 1, 2

## JMK105C6225KV-F
designator C?  Capacitance: 2.2uF  (hidden comment: *)
Capacitor, Ceramic (MLCC), 2.2uF, ±10%, 6.3V, X6S, ±10%, SMD 0402; Manufacturer: Taiyo Yuden; Manufacturer Part Number: JMK105C6225KV-F
footprint CAP-0402 (0402 (1005M) Capacitor)
pins: 1, 2

## JMK105CBJ106MV-F
designator C?  Capacitance: 10uF  (hidden comment: *)
Capacitor, Ceramic (MLCC), 10uF, ±20%, 6.3V, X5R, ±20%, SMD 0402; Manufacturer: Taiyo Yuden; Manufacturer Part Number: JMK105CBJ106MV-F
footprint CAP-0402 (0402 (1005M) Capacitor)
pins: 1, 2

## LDK105CBJ106MVLF
designator C?  Capacitance: 10uF  (hidden comment: *)
Capacitor, Ceramic (MLCC), 10uF, ±20%, 10V, X5R, ±20%, SMD 0402; Manufacturer: Taiyo Yuden; Manufacturer Part Number: LDK105CBJ106MVLF
footprint CAP-0402 (0402 (1005M) Capacitor)
pins: 1, 2

## LLD153D80G105ME01D
designator C?  Capacitance: 1uF  (hidden comment: *)
Capacitor, Ceramic (MLCC), 1uF, ±20%, 4V, X6T, ±20%, SMD 0402; Manufacturer: Murata Electronics; Manufacturer Part Number: LLD153D80G105ME01D
footprint CAP-0402 (0402 (1005M) Capacitor)
pins: 1, 2

## LMK105ABJ225KVHF
designator C?  Capacitance: 2.2uF  (hidden comment: *)
Capacitor, Ceramic (MLCC), 2.2uF, ±10%, 10V, X5R, ±10%, SMD 0402; Manufacturer: Taiyo Yuden; Manufacturer Part Number: LMK105ABJ225KVHF
footprint CAP-0402 (0402 (1005M) Capacitor)
pins: 1, 2

## LMK105ABJ225MVHF
designator C?  Capacitance: 2.2uF  (hidden comment: *)
Capacitor, Ceramic (MLCC), 2.2uF, ±20%, 10V, X5R, ±20%, SMD 0402; Manufacturer: Taiyo Yuden; Manufacturer Part Number: LMK105ABJ225MVHF
footprint CAP-0402 (0402 (1005M) Capacitor)
pins: 1, 2

## LMK105B7224KVHF
designator C?  Capacitance: 220nF  (hidden comment: *)
Capacitor, Ceramic (MLCC), 220nF, ±10%, 10V, X7R, ±10%, SMD 0402; Manufacturer: Taiyo Yuden; Manufacturer Part Number: LMK105B7224KVHF
footprint CAP-0402 (0402 (1005M) Capacitor)
pins: 1, 2

## LMK105B7474KV-F
designator C?  Capacitance: 470nF  (hidden comment: *)
Capacitor, Ceramic (MLCC), 470nF, ±10%, 10V, X7R, ±10%, SMD 0402; Manufacturer: Taiyo Yuden; Manufacturer Part Number: LMK105B7474KV-F
footprint CAP-0402 (0402 (1005M) Capacitor)
pins: 1, 2

## LMK105BBJ475MVLF
designator C?  Capacitance: 4.7uF  (hidden comment: *)
Capacitor, Ceramic (MLCC), 4.7uF, ±20%, 10V, X5R, ±20%, SMD 0402; Manufacturer: Taiyo Yuden; Manufacturer Part Number: LMK105BBJ475MVLF
footprint CAP-0402 (0402 (1005M) Capacitor)
pins: 1, 2

## LMK105BJ105KV-F
designator C?  Capacitance: 1uF  (hidden comment: *)
Capacitor, Ceramic (MLCC), 1uF, ±10%, 10V, X5R, ±10%, SMD 0402; Manufacturer: Taiyo Yuden; Manufacturer Part Number: LMK105BJ105KV-F
footprint CAP-0402 (0402 (1005M) Capacitor)
pins: 1, 2

## LMK105BJ105KVBF
designator C?  Capacitance: 1uF  (hidden comment: *)
Capacitor, Ceramic (MLCC), 1uF, ±10%, 10V, X5R, ±10%, SMD 0402; Manufacturer: Taiyo Yuden; Manufacturer Part Number: LMK105BJ105KVBF
footprint CAP-0402 (0402 (1005M) Capacitor)
pins: 1, 2

## LMK105BJ105KVHF
designator C?  Capacitance: 1uF  (hidden comment: *)
Capacitor, Ceramic (MLCC), 1uF, ±10%, 10V, X5R, ±10%, SMD 0402; Manufacturer: Taiyo Yuden; Manufacturer Part Number: LMK105BJ105KVHF
footprint CAP-0402 (0402 (1005M) Capacitor)
pins: 1, 2

## LMK105BJ224KV-F
designator C?  Capacitance: 220nF  (hidden comment: *)
Capacitor, Ceramic (MLCC), 220nF, ±10%, 10V, X5R, ±10%, SMD 0402; Manufacturer: Taiyo Yuden; Manufacturer Part Number: LMK105BJ224KV-F
footprint CAP-0402 (0402 (1005M) Capacitor)
pins: 1, 2

## LMK105BJ225KV-F
designator C?  Capacitance: 2.2uF  (hidden comment: *)
Capacitor, Ceramic (MLCC), 2.2uF, ±10%, 10V, X5R, ±10%, SMD 0402; Manufacturer: Taiyo Yuden; Manufacturer Part Number: LMK105BJ225KV-F
footprint CAP-0402 (0402 (1005M) Capacitor)
pins: 1, 2

## LMK105BJ225MV-F
designator C?  Capacitance: 2.2uF  (hidden comment: *)
Capacitor, Ceramic (MLCC), 2.2uF, ±20%, 10V, X5R, ±20%, SMD 0402; Manufacturer: Taiyo Yuden; Manufacturer Part Number: LMK105BJ225MV-F
footprint CAP-0402 (0402 (1005M) Capacitor)
pins: 1, 2

## LMK105BJ473KV-F
designator C?  Capacitance: 47nF  (hidden comment: *)
Capacitor, Ceramic (MLCC), 47nF, ±10%, 10V, X5R, ±10%, SMD 0402; Manufacturer: Taiyo Yuden; Manufacturer Part Number: LMK105BJ473KV-F
footprint CAP-0402 (0402 (1005M) Capacitor)
pins: 1, 2

## LMK105BJ474KV-F
designator C?  Capacitance: 470nF  (hidden comment: *)
Capacitor, Ceramic (MLCC), 470nF, ±10%, 10V, X5R, ±10%, SMD 0402; Manufacturer: Taiyo Yuden; Manufacturer Part Number: LMK105BJ474KV-F
footprint CAP-0402 (0402 (1005M) Capacitor)
pins: 1, 2

## LMK105C6105KV-F
designator C?  Capacitance: 1uF  (hidden comment: *)
Capacitor, Ceramic (MLCC), 1uF, ±10%, 10V, X6S, ±10%, SMD 0402; Manufacturer: Taiyo Yuden; Manufacturer Part Number: LMK105C6105KV-F
footprint CAP-0402 (0402 (1005M) Capacitor)
pins: 1, 2

## LMK105SD472JV-F
designator C?  Capacitance: 4.7nF  (hidden comment: *)
Capacitor, Ceramic (MLCC), 4.7nF, ±5%, 10V, ±5%, SMD 0402; Manufacturer: Taiyo Yuden; Manufacturer Part Number: LMK105SD472JV-F
footprint CAP-0402 (0402 (1005M) Capacitor)
pins: 1, 2

## MG15B102K500CT
designator C?  Capacitance: 1nF  (hidden comment: *)
Capacitor, Ceramic (MLCC), 1nF, ±10%, 50V, X7R, ±10%, SMD 0402; Manufacturer: Walsin Tech Corp; Manufacturer Part Number: MG15B102K500CT
footprint CAP-0402 (0402 (1005M) Capacitor)
pins: 1, 2

## MG15B103K500CT
designator C?  Capacitance: 10nF  (hidden comment: *)
Capacitor, Ceramic (MLCC), 10nF, ±10%, 50V, X7R, ±10%, SMD 0402; Manufacturer: Walsin Tech Corp; Manufacturer Part Number: MG15B103K500CT
footprint CAP-0402 (0402 (1005M) Capacitor)
pins: 1, 2

## MG15B104K160CT
designator C?  Capacitance: 100nF  (hidden comment: *)
Capacitor, Ceramic (MLCC), 100nF, ±10%, 16V, X7R, ±10%, SMD 0402; Manufacturer: Walsin Tech Corp; Manufacturer Part Number: MG15B104K160CT
footprint CAP-0402 (0402 (1005M) Capacitor)
pins: 1, 2

## MG15B221K500CT
designator C?  Capacitance: 220pF  (hidden comment: *)
Capacitor, Ceramic (MLCC), 220pF, ±10%, 50V, X7R, ±10%, SMD 0402; Manufacturer: Walsin Tech Corp; Manufacturer Part Number: MG15B221K500CT
footprint CAP-0402 (0402 (1005M) Capacitor)
pins: 1, 2

## MG15N100J500CT
designator C?  Capacitance: 10pF  (hidden comment: *)
Capacitor, Ceramic (MLCC), 10pF, ±5%, 50V, NP0, ±5%, SMD 0402; Manufacturer: Walsin Tech Corp; Manufacturer Part Number: MG15N100J500CT
footprint CAP-0402 (0402 (1005M) Capacitor)
pins: 1, 2

## MG15N101J500CT
designator C?  Capacitance: 100pF  (hidden comment: *)
Capacitor, Ceramic (MLCC), 100pF, ±5%, 50V, NP0, ±5%, SMD 0402; Manufacturer: Walsin Tech Corp; Manufacturer Part Number: MG15N101J500CT
footprint CAP-0402 (0402 (1005M) Capacitor)
pins: 1, 2

## MG15N120J500CT
designator C?  Capacitance: 12pF  (hidden comment: *)
Capacitor, Ceramic (MLCC), 12pF, ±5%, 50V, NP0, ±5%, SMD 0402; Manufacturer: Walsin Tech Corp; Manufacturer Part Number: MG15N120J500CT
footprint CAP-0402 (0402 (1005M) Capacitor)
pins: 1, 2

## MG15N150J500CT
designator C?  Capacitance: 15pF  (hidden comment: *)
Capacitor, Ceramic (MLCC), 15pF, ±5%, 50V, NP0, ±5%, SMD 0402; Manufacturer: Walsin Tech Corp; Manufacturer Part Number: MG15N150J500CT
footprint CAP-0402 (0402 (1005M) Capacitor)
pins: 1, 2

## MG15N220J500CT
designator C?  Capacitance: 22pF  (hidden comment: *)
Capacitor, Ceramic (MLCC), 22pF, ±5%, 50V, NP0, ±5%, SMD 0402; Manufacturer: Walsin Tech Corp; Manufacturer Part Number: MG15N220J500CT
footprint CAP-0402 (0402 (1005M) Capacitor)
pins: 1, 2

## MG15N221J500CT
designator C?  Capacitance: 220pF  (hidden comment: *)
Capacitor, Ceramic (MLCC), 220pF, ±5%, 50V, NP0, ±5%, SMD 0402; Manufacturer: Walsin Tech Corp; Manufacturer Part Number: MG15N221J500CT
footprint CAP-0402 (0402 (1005M) Capacitor)
pins: 1, 2

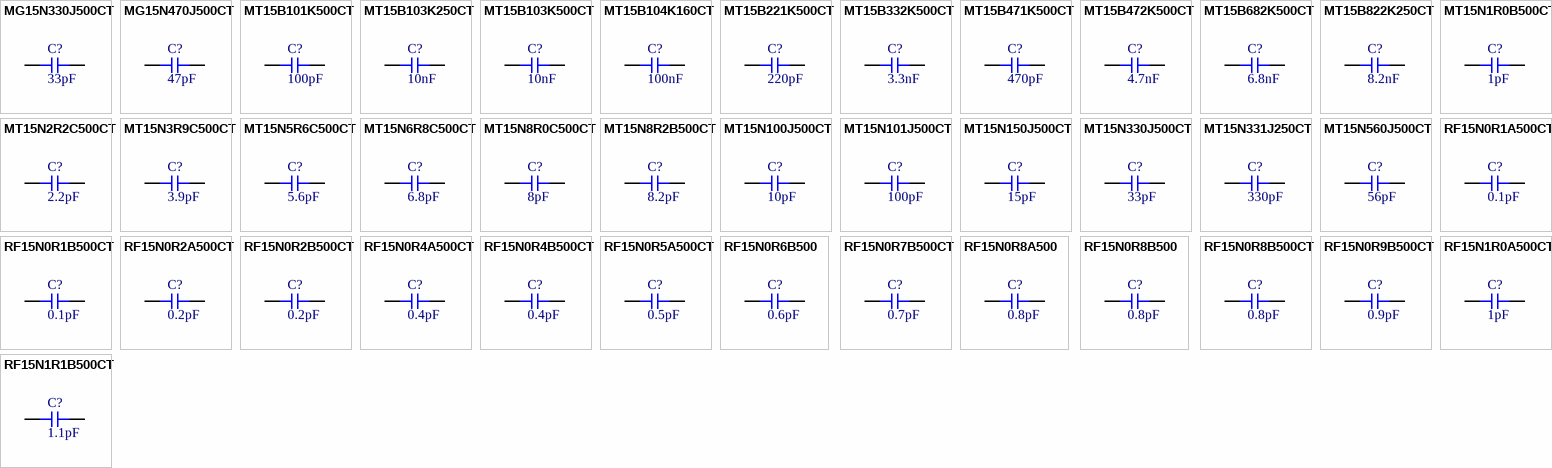
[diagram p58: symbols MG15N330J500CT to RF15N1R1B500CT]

## MG15N330J500CT
designator C?  Capacitance: 33pF  (hidden comment: *)
Capacitor, Ceramic (MLCC), 33pF, ±5%, 50V, NP0, ±5%, SMD 0402; Manufacturer: Walsin Tech Corp; Manufacturer Part Number: MG15N330J500CT
footprint CAP-0402 (0402 (1005M) Capacitor)
pins: 1, 2

## MG15N470J500CT
designator C?  Capacitance: 47pF  (hidden comment: *)
Capacitor, Ceramic (MLCC), 47pF, ±5%, 50V, NP0, ±5%, SMD 0402; Manufacturer: Walsin Tech Corp; Manufacturer Part Number: MG15N470J500CT
footprint CAP-0402 (0402 (1005M) Capacitor)
pins: 1, 2

## MT15B101K500CT
designator C?  Capacitance: 100pF  (hidden comment: *)
Capacitor, Ceramic (MLCC), 100pF, ±10%, 50V, X7R, ±10%, SMD 0402; Manufacturer: Walsin Tech Corp; Manufacturer Part Number: MT15B101K500CT
footprint CAP-0402 (0402 (1005M) Capacitor)
pins: 1, 2

## MT15B103K250CT
designator C?  Capacitance: 10nF  (hidden comment: *)
Capacitor, Ceramic (MLCC), 10nF, ±10%, 25V, X7R, ±10%, SMD 0402; Manufacturer: Walsin Tech Corp; Manufacturer Part Number: MT15B103K250CT
footprint CAP-0402 (0402 (1005M) Capacitor)
pins: 1, 2

## MT15B103K500CT
designator C?  Capacitance: 10nF  (hidden comment: *)
Capacitor, Ceramic (MLCC), 10nF, ±10%, 50V, X7R, ±10%, SMD 0402; Manufacturer: Walsin Tech Corp; Manufacturer Part Number: MT15B103K500CT
footprint CAP-0402 (0402 (1005M) Capacitor)
pins: 1, 2

## MT15B104K160CT
designator C?  Capacitance: 100nF  (hidden comment: *)
Capacitor, Ceramic (MLCC), 100nF, ±10%, 16V, X7R, ±10%, SMD 0402; Manufacturer: Walsin Tech Corp; Manufacturer Part Number: MT15B104K160CT
footprint CAP-0402 (0402 (1005M) Capacitor)
pins: 1, 2

## MT15B221K500CT
designator C?  Capacitance: 220pF  (hidden comment: *)
Capacitor, Ceramic (MLCC), 220pF, ±10%, 50V, X7R, ±10%, SMD 0402; Manufacturer: Walsin Tech Corp; Manufacturer Part Number: MT15B221K500CT
footprint CAP-0402 (0402 (1005M) Capacitor)
pins: 1, 2

## MT15B332K500CT
designator C?  Capacitance: 3.3nF  (hidden comment: *)
Capacitor, Ceramic (MLCC), 3.3nF, ±10%, 50V, X7R, ±10%, SMD 0402; Manufacturer: Walsin Tech Corp; Manufacturer Part Number: MT15B332K500CT
footprint CAP-0402 (0402 (1005M) Capacitor)
pins: 1, 2

## MT15B471K500CT
designator C?  Capacitance: 470pF  (hidden comment: *)
Capacitor, Ceramic (MLCC), 470pF, ±10%, 50V, X7R, ±10%, SMD 0402; Manufacturer: Walsin Tech Corp; Manufacturer Part Number: MT15B471K500CT
footprint CAP-0402 (0402 (1005M) Capacitor)
pins: 1, 2

## MT15B472K500CT
designator C?  Capacitance: 4.7nF  (hidden comment: *)
Capacitor, Ceramic (MLCC), 4.7nF, ±10%, 50V, X7R, ±10%, SMD 0402; Manufacturer: Walsin Tech Corp; Manufacturer Part Number: MT15B472K500CT
footprint CAP-0402 (0402 (1005M) Capacitor)
pins: 1, 2

## MT15B682K500CT
designator C?  Capacitance: 6.8nF  (hidden comment: *)
Capacitor, Ceramic (MLCC), 6.8nF, ±10%, 50V, X7R, ±10%, SMD 0402; Manufacturer: Walsin Tech Corp; Manufacturer Part Number: MT15B682K500CT
footprint CAP-0402 (0402 (1005M) Capacitor)
pins: 1, 2

## MT15B822K250CT
designator C?  Capacitance: 8.2nF  (hidden comment: *)
Capacitor, Ceramic (MLCC), 8.2nF, ±10%, 25V, X7R, ±10%, SMD 0402; Manufacturer: Walsin Tech Corp; Manufacturer Part Number: MT15B822K250CT
footprint CAP-0402 (0402 (1005M) Capacitor)
pins: 1, 2

## MT15N1R0B500CT
designator C?  Capacitance: 1pF  (hidden comment: *)
Capacitor, Ceramic (MLCC), 1pF, ±0.1pF, 50V, NP0, ±0.1pF, SMD 0402; Manufacturer: Walsin Tech Corp; Manufacturer Part Number: MT15N1R0B500CT
footprint CAP-0402 (0402 (1005M) Capacitor)
pins: 1, 2

## MT15N2R2C500CT
designator C?  Capacitance: 2.2pF  (hidden comment: *)
Capacitor, Ceramic (MLCC), 2.2pF, ±0.25pF, 50V, NP0, ±0.25pF, SMD 0402; Manufacturer: Walsin Tech Corp; Manufacturer Part Number: MT15N2R2C500CT
footprint CAP-0402 (0402 (1005M) Capacitor)
pins: 1, 2

## MT15N3R9C500CT
designator C?  Capacitance: 3.9pF  (hidden comment: *)
Capacitor, Ceramic (MLCC), 3.9pF, ±0.25pF, 50V, NP0, ±0.25pF, SMD 0402; Manufacturer: Walsin Tech Corp; Manufacturer Part Number: MT15N3R9C500CT
footprint CAP-0402 (0402 (1005M) Capacitor)
pins: 1, 2

## MT15N5R6C500CT
designator C?  Capacitance: 5.6pF  (hidden comment: *)
Capacitor, Ceramic (MLCC), 5.6pF, ±0.25pF, 50V, NP0, ±0.25pF, SMD 0402; Manufacturer: Walsin Tech Corp; Manufacturer Part Number: MT15N5R6C500CT
footprint CAP-0402 (0402 (1005M) Capacitor)
pins: 1, 2

## MT15N6R8C500CT
designator C?  Capacitance: 6.8pF  (hidden comment: *)
Capacitor, Ceramic (MLCC), 6.8pF, ±0.25pF, 50V, NP0, ±0.25pF, SMD 0402; Manufacturer: Walsin Tech Corp; Manufacturer Part Number: MT15N6R8C500CT
footprint CAP-0402 (0402 (1005M) Capacitor)
pins: 1, 2

## MT15N8R0C500CT
designator C?  Capacitance: 8pF  (hidden comment: *)
Capacitor, Ceramic (MLCC), 8pF, ±0.25pF, 50V, NP0, ±0.25pF, SMD 0402; Manufacturer: Walsin Tech Corp; Manufacturer Part Number: MT15N8R0C500CT
footprint CAP-0402 (0402 (1005M) Capacitor)
pins: 1, 2

## MT15N8R2B500CT
designator C?  Capacitance: 8.2pF  (hidden comment: *)
Capacitor, Ceramic (MLCC), 8.2pF, ±0.1pF, 50V, NP0, ±0.1pF, SMD 0402; Manufacturer: Walsin Tech Corp; Manufacturer Part Number: MT15N8R2B500CT
footprint CAP-0402 (0402 (1005M) Capacitor)
pins: 1, 2

## MT15N100J500CT
designator C?  Capacitance: 10pF  (hidden comment: *)
Capacitor, Ceramic (MLCC), 10pF, ±5%, 50V, NP0, ±5%, SMD 0402; Manufacturer: Walsin Tech Corp; Manufacturer Part Number: MT15N100J500CT
footprint CAP-0402 (0402 (1005M) Capacitor)
pins: 1, 2

## MT15N101J500CT
designator C?  Capacitance: 100pF  (hidden comment: *)
Capacitor, Ceramic (MLCC), 100pF, ±5%, 50V, NP0, ±5%, SMD 0402; Manufacturer: Walsin Tech Corp; Manufacturer Part Number: MT15N101J500CT
footprint CAP-0402 (0402 (1005M) Capacitor)
pins: 1, 2

## MT15N150J500CT
designator C?  Capacitance: 15pF  (hidden comment: *)
Capacitor, Ceramic (MLCC), 15pF, ±5%, 50V, NP0, ±5%, SMD 0402; Manufacturer: Walsin Tech Corp; Manufacturer Part Number: MT15N150J500CT
footprint CAP-0402 (0402 (1005M) Capacitor)
pins: 1, 2

## MT15N330J500CT
designator C?  Capacitance: 33pF  (hidden comment: *)
Capacitor, Ceramic (MLCC), 33pF, ±5%, 50V, NP0, ±5%, SMD 0402; Manufacturer: Walsin Tech Corp; Manufacturer Part Number: MT15N330J500CT
footprint CAP-0402 (0402 (1005M) Capacitor)
pins: 1, 2

## MT15N331J250CT
designator C?  Capacitance: 330pF  (hidden comment: *)
Capacitor, Ceramic (MLCC), 330pF, ±5%, 25V, NP0, ±5%, SMD 0402; Manufacturer: Walsin Tech Corp; Manufacturer Part Number: MT15N331J250CT
footprint CAP-0402 (0402 (1005M) Capacitor)
pins: 1, 2

## MT15N560J500CT
designator C?  Capacitance: 56pF  (hidden comment: *)
Capacitor, Ceramic (MLCC), 56pF, ±5%, 50V, NP0, ±5%, SMD 0402; Manufacturer: Walsin Tech Corp; Manufacturer Part Number: MT15N560J500CT
footprint CAP-0402 (0402 (1005M) Capacitor)
pins: 1, 2

## RF15N0R1A500CT
designator C?  Capacitance: 0.1pF  (hidden comment: *)
Capacitor, Ceramic (MLCC), 0.1pF, ±0.05pF, 50V, NP0, ±0.05pF, SMD 0402; Manufacturer: Walsin Tech Corp; Manufacturer Part Number: RF15N0R1A500CT
footprint CAP-0402 (0402 (1005M) Capacitor)
pins: 1, 2

## RF15N0R1B500CT
designator C?  Capacitance: 0.1pF  (hidden comment: *)
Capacitor, Ceramic (MLCC), 0.1pF, ±0.1pF, 50V, NP0, ±0.1pF, SMD 0402; Manufacturer: Walsin Tech Corp; Manufacturer Part Number: RF15N0R1B500CT
footprint CAP-0402 (0402 (1005M) Capacitor)
pins: 1, 2

## RF15N0R2A500CT
designator C?  Capacitance: 0.2pF  (hidden comment: *)
Capacitor, Ceramic (MLCC), 0.2pF, ±0.05pF, 50V, NP0, ±0.05pF, SMD 0402; Manufacturer: Walsin Tech Corp; Manufacturer Part Number: RF15N0R2A500CT
footprint CAP-0402 (0402 (1005M) Capacitor)
pins: 1, 2

## RF15N0R2B500CT
designator C?  Capacitance: 0.2pF  (hidden comment: *)
Capacitor, Ceramic (MLCC), 0.2pF, ±0.1pF, 50V, NP0, ±0.1pF, SMD 0402; Manufacturer: Walsin Tech Corp; Manufacturer Part Number: RF15N0R2B500CT
footprint CAP-0402 (0402 (1005M) Capacitor)
pins: 1, 2

## RF15N0R4A500CT
designator C?  Capacitance: 0.4pF  (hidden comment: *)
Capacitor, Ceramic (MLCC), 0.4pF, ±0.05pF, 50V, NP0, ±0.05pF, SMD 0402; Manufacturer: Walsin Tech Corp; Manufacturer Part Number: RF15N0R4A500CT
footprint CAP-0402 (0402 (1005M) Capacitor)
pins: 1, 2

## RF15N0R4B500CT
designator C?  Capacitance: 0.4pF  (hidden comment: *)
Capacitor, Ceramic (MLCC), 0.4pF, ±0.1pF, 50V, NP0, ±0.1pF, SMD 0402; Manufacturer: Walsin Tech Corp; Manufacturer Part Number: RF15N0R4B500CT
footprint CAP-0402 (0402 (1005M) Capacitor)
pins: 1, 2

## RF15N0R5A500CT
designator C?  Capacitance: 0.5pF  (hidden comment: *)
Capacitor, Ceramic (MLCC), 0.5pF, ±0.05pF, 50V, NP0, ±0.05pF, SMD 0402; Manufacturer: Walsin Tech Corp; Manufacturer Part Number: RF15N0R5A500CT
footprint CAP-0402 (0402 (1005M) Capacitor)
pins: 1, 2

## RF15N0R6B500
designator C?  Capacitance: 0.6pF  (hidden comment: *)
Capacitor, Ceramic (MLCC), 0.6pF, ±0.1pF, 50V, NP0, ±0.1pF, SMD 0402; Manufacturer: Walsin Tech Corp; Manufacturer Part Number: RF15N0R6B500
footprint CAP-0402 (0402 (1005M) Capacitor)
pins: 1, 2

## RF15N0R7B500CT
designator C?  Capacitance: 0.7pF  (hidden comment: *)
Capacitor, Ceramic (MLCC), 0.7pF, ±0.1pF, 50V, NP0, ±0.1pF, SMD 0402; Manufacturer: Walsin Tech Corp; Manufacturer Part Number: RF15N0R7B500CT
footprint CAP-0402 (0402 (1005M) Capacitor)
pins: 1, 2

## RF15N0R8A500
designator C?  Capacitance: 0.8pF  (hidden comment: *)
Capacitor, Ceramic (MLCC), 0.8pF, ±0.05pF, 50V, NP0, ±0.05pF, SMD 0402; Manufacturer: Walsin Tech Corp; Manufacturer Part Number: RF15N0R8A500
footprint CAP-0402 (0402 (1005M) Capacitor)
pins: 1, 2

## RF15N0R8B500
designator C?  Capacitance: 0.8pF  (hidden comment: *)
Capacitor, Ceramic (MLCC), 0.8pF, ±0.1pF, 50V, NP0, ±0.1pF, SMD 0402; Manufacturer: Walsin Tech Corp; Manufacturer Part Number: RF15N0R8B500
footprint CAP-0402 (0402 (1005M) Capacitor)
pins: 1, 2

## RF15N0R8B500CT
designator C?  Capacitance: 0.8pF  (hidden comment: *)
Capacitor, Ceramic (MLCC), 0.8pF, ±0.1pF, 50V, NP0, ±0.1pF, SMD 0402; Manufacturer: Walsin Tech Corp; Manufacturer Part Number: RF15N0R8B500CT
footprint CAP-0402 (0402 (1005M) Capacitor)
pins: 1, 2

## RF15N0R9B500CT
designator C?  Capacitance: 0.9pF  (hidden comment: *)
Capacitor, Ceramic (MLCC), 0.9pF, ±0.1pF, 50V, NP0, ±0.1pF, SMD 0402; Manufacturer: Walsin Tech Corp; Manufacturer Part Number: RF15N0R9B500CT
footprint CAP-0402 (0402 (1005M) Capacitor)
pins: 1, 2

## RF15N1R0A500CT
designator C?  Capacitance: 1pF  (hidden comment: *)
Capacitor, Ceramic (MLCC), 1pF, ±0.05pF, 50V, NP0, ±0.05pF, SMD 0402; Manufacturer: Walsin Tech Corp; Manufacturer Part Number: RF15N1R0A500CT
footprint CAP-0402 (0402 (1005M) Capacitor)
pins: 1, 2

## RF15N1R1B500CT
designator C?  Capacitance: 1.1pF  (hidden comment: *)
Capacitor, Ceramic (MLCC), 1.1pF, ±0.1pF, 50V, NP0, ±0.1pF, SMD 0402; Manufacturer: Walsin Tech Corp; Manufacturer Part Number: RF15N1R1B500CT
footprint CAP-0402 (0402 (1005M) Capacitor)
pins: 1, 2

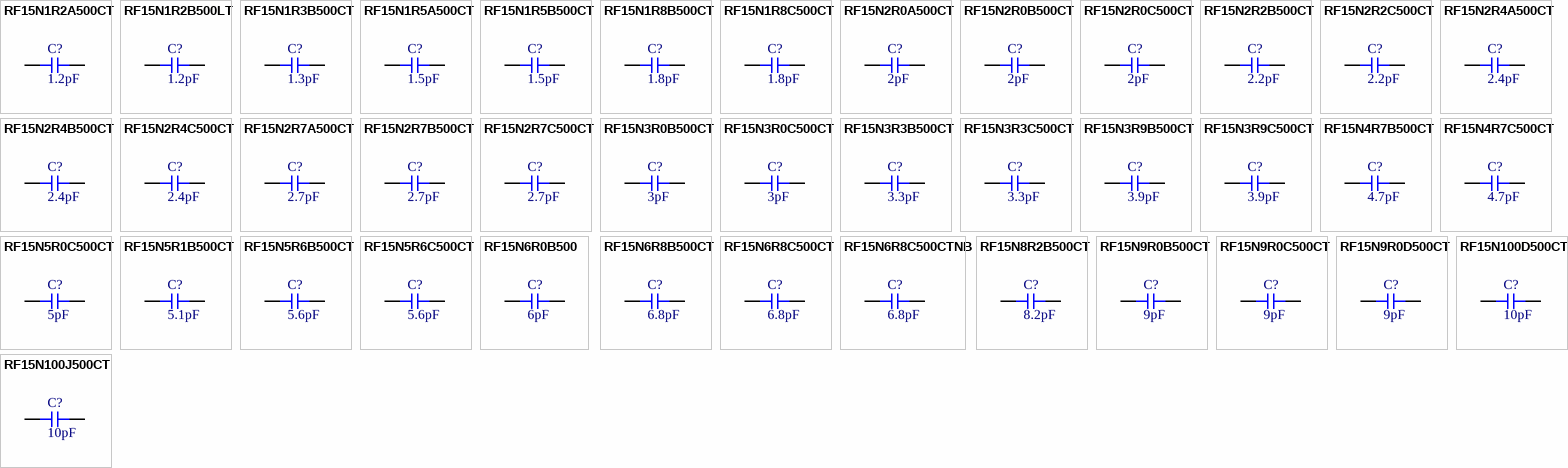
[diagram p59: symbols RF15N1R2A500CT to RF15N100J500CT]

## RF15N1R2A500CT
designator C?  Capacitance: 1.2pF  (hidden comment: *)
Capacitor, Ceramic (MLCC), 1.2pF, ±0.05pF, 50V, NP0, ±0.05pF, SMD 0402; Manufacturer: Walsin Tech Corp; Manufacturer Part Number: RF15N1R2A500CT
footprint CAP-0402 (0402 (1005M) Capacitor)
pins: 1, 2

## RF15N1R2B500LT
designator C?  Capacitance: 1.2pF  (hidden comment: *)
Capacitor, Ceramic (MLCC), 1.2pF, ±0.1pF, 50V, NP0, ±0.1pF, SMD 0402; Manufacturer: Walsin Tech Corp; Manufacturer Part Number: RF15N1R2B500LT
footprint CAP-0402 (0402 (1005M) Capacitor)
pins: 1, 2

## RF15N1R3B500CT
designator C?  Capacitance: 1.3pF  (hidden comment: *)
Capacitor, Ceramic (MLCC), 1.3pF, ±0.1pF, 50V, NP0, ±0.1pF, SMD 0402; Manufacturer: Walsin Tech Corp; Manufacturer Part Number: RF15N1R3B500CT
footprint CAP-0402 (0402 (1005M) Capacitor)
pins: 1, 2

## RF15N1R5A500CT
designator C?  Capacitance: 1.5pF  (hidden comment: *)
Capacitor, Ceramic (MLCC), 1.5pF, ±0.05pF, 50V, NP0, ±0.05pF, SMD 0402; Manufacturer: Walsin Tech Corp; Manufacturer Part Number: RF15N1R5A500CT
footprint CAP-0402 (0402 (1005M) Capacitor)
pins: 1, 2

## RF15N1R5B500CT
designator C?  Capacitance: 1.5pF  (hidden comment: *)
Capacitor, Ceramic (MLCC), 1.5pF, ±0.1pF, 50V, NP0, ±0.1pF, SMD 0402; Manufacturer: Walsin Tech Corp; Manufacturer Part Number: RF15N1R5B500CT
footprint CAP-0402 (0402 (1005M) Capacitor)
pins: 1, 2

## RF15N1R8B500CT
designator C?  Capacitance: 1.8pF  (hidden comment: *)
Capacitor, Ceramic (MLCC), 1.8pF, ±0.1pF, 50V, NP0, ±0.1pF, SMD 0402; Manufacturer: Walsin Tech Corp; Manufacturer Part Number: RF15N1R8B500CT
footprint CAP-0402 (0402 (1005M) Capacitor)
pins: 1, 2

## RF15N1R8C500CT
designator C?  Capacitance: 1.8pF  (hidden comment: *)
Capacitor, Ceramic (MLCC), 1.8pF, ±0.25pF, 50V, NP0, ±0.25pF, SMD 0402; Manufacturer: Walsin Tech Corp; Manufacturer Part Number: RF15N1R8C500CT
footprint CAP-0402 (0402 (1005M) Capacitor)
pins: 1, 2

## RF15N2R0A500CT
designator C?  Capacitance: 2pF  (hidden comment: *)
Capacitor, Ceramic (MLCC), 2pF, ±0.05pF, 50V, NP0, ±0.05pF, SMD 0402; Manufacturer: Walsin Tech Corp; Manufacturer Part Number: RF15N2R0A500CT
footprint CAP-0402 (0402 (1005M) Capacitor)
pins: 1, 2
